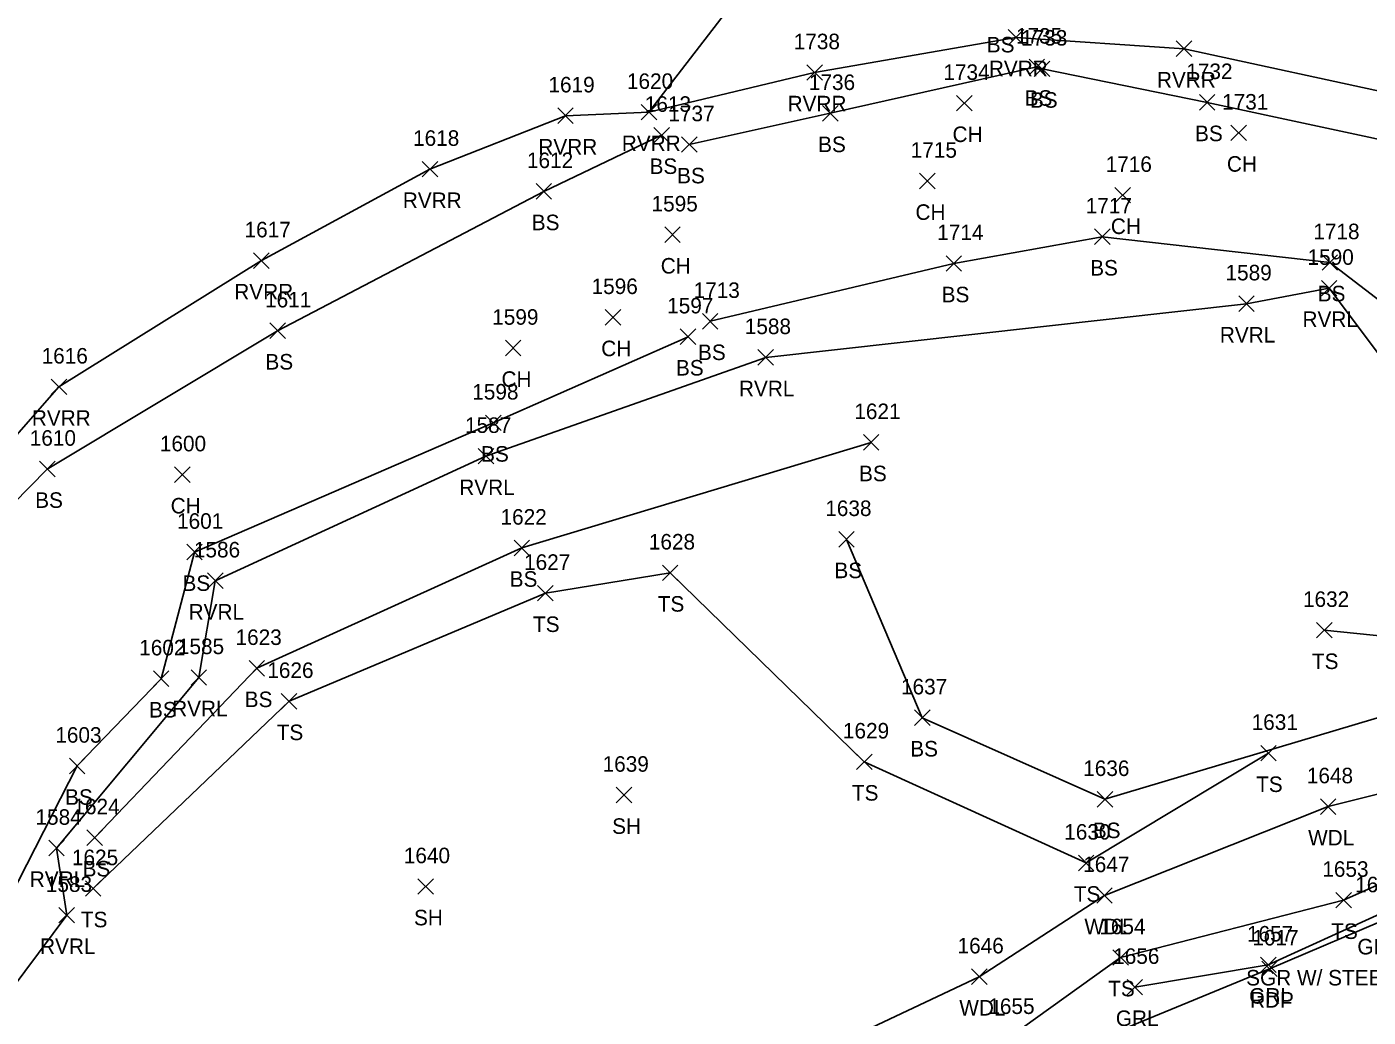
# Model space of a CAD drawing. Extents: x 1633660 to 1636532, y 388643 to 392631.
# Drawn here: x 1634224 to 1634396.6, y 388922.1 to 389049.6 of the extents above; entities that cross this region are included whole.
import ezdxf

# ---------------------------------------------------------------- set-up
doc = ezdxf.new("R2010")
doc.units = 0
for name, color, linetype in [('L_A', 7, 'Continuous'), ('L_I', 7, 'Continuous'), ('L_TIC', 7, 'Continuous'), ('LAWA', 7, 'Continuous'), ('LAWE', 7, 'Continuous'), ('LELB', 7, 'Continuous'), ('LSOGP', 7, 'Continuous'), ('P_A', 7, 'Continuous'), ('P_I', 7, 'Continuous'), ('P_TIC', 7, 'Continuous'), ('PET', 7, 'Continuous'), ('R_A', 7, 'Continuous'), ('R_C', 7, 'Continuous'), ('R_I', 7, 'Continuous'), ('R_TIC', 7, 'Continuous'), ('RGR', 7, 'Continuous')]:
    doc.layers.add(name, color=color, linetype=linetype)

msp = doc.modelspace()

# ---------------------------------------------------------------- linework, layer by layer
at = {"layer": 'L_TIC'}
for points in [[(1634350.31, 389047.27), (1634352.31, 389049.27)], [(1634352.31, 389047.27), (1634350.31, 389049.27)], [(1634371.94, 389045.82), (1634373.94, 389047.82)], [(1634373.94, 389045.82), (1634371.94, 389047.82)], [(1634352.99, 389043.47), (1634354.99, 389045.47)], [(1634354.99, 389043.47), (1634352.99, 389045.47)], [(1634353.66, 389043.22), (1634355.66, 389045.22)], [(1634355.66, 389043.22), (1634353.66, 389045.22)], [(1634324.39, 389042.75), (1634326.39, 389044.75)], [(1634326.39, 389042.75), (1634324.39, 389044.75)], [(1634343.65, 389038.8), (1634345.65, 389040.8)], [(1634345.65, 389038.8), (1634343.65, 389040.8)], [(1634374.92, 389038.91), (1634376.92, 389040.91)], [(1634376.92, 389038.91), (1634374.92, 389040.91)], [(1634292.32, 389037.19), (1634294.32, 389039.19)], [(1634294.32, 389037.19), (1634292.32, 389039.19)], [(1634303.06, 389037.64), (1634305.06, 389039.64)], [(1634305.06, 389037.64), (1634303.06, 389039.64)], [(1634326.4, 389037.5), (1634328.4, 389039.5)], [(1634328.4, 389037.5), (1634326.4, 389039.5)], [(1634304.7, 389034.69), (1634306.7, 389036.69)], [(1634306.7, 389034.69), (1634304.7, 389036.69)], [(1634378.97, 389034.98), (1634380.97, 389036.98)], [(1634380.97, 389034.98), (1634378.97, 389036.98)], [(1634308.25, 389033.48), (1634310.25, 389035.48)], [(1634310.25, 389033.48), (1634308.25, 389035.48)], [(1634274.87, 389030.31), (1634276.87, 389032.31)], [(1634276.87, 389030.31), (1634274.87, 389032.31)], [(1634338.89, 389028.78), (1634340.89, 389030.78)], [(1634340.89, 389028.78), (1634338.89, 389030.78)], [(1634289.54, 389027.45), (1634291.54, 389029.45)], [(1634291.54, 389027.45), (1634289.54, 389029.45)], [(1634364.03, 389026.96), (1634366.03, 389028.96)], [(1634366.03, 389026.96), (1634364.03, 389028.96)], [(1634306.09, 389021.87), (1634308.09, 389023.87)], [(1634308.09, 389021.87), (1634306.09, 389023.87)], [(1634361.42, 389021.61), (1634363.42, 389023.61)], [(1634363.42, 389021.61), (1634361.42, 389023.61)], [(1634253.18, 389018.53), (1634255.18, 389020.53)], [(1634255.18, 389018.53), (1634253.18, 389020.53)], [(1634342.3, 389018.17), (1634344.3, 389020.17)], [(1634344.3, 389018.17), (1634342.3, 389020.17)], [(1634390.71, 389018.29), (1634392.71, 389020.29)], [(1634392.71, 389018.29), (1634390.71, 389020.29)], [(1634390.62, 389014.99), (1634392.62, 389016.99)], [(1634392.62, 389014.99), (1634390.62, 389016.99)], [(1634379.98, 389012.99), (1634381.98, 389014.99)], [(1634381.98, 389012.99), (1634379.98, 389014.99)], [(1634298.43, 389011.23), (1634300.43, 389013.23)], [(1634300.43, 389011.23), (1634298.43, 389013.23)], [(1634310.94, 389010.73), (1634312.94, 389012.73)], [(1634312.94, 389010.73), (1634310.94, 389012.73)], [(1634255.26, 389009.51), (1634257.26, 389011.51)], [(1634257.26, 389009.51), (1634255.26, 389011.51)], [(1634308.1, 389008.74), (1634310.1, 389010.74)], [(1634310.1, 389008.74), (1634308.1, 389010.74)], [(1634285.59, 389007.28), (1634287.59, 389009.28)], [(1634287.59, 389007.28), (1634285.59, 389009.28)], [(1634318.09, 389006.07), (1634320.09, 389008.07)], [(1634320.09, 389006.07), (1634318.09, 389008.07)], [(1634227.12, 389002.28), (1634229.12, 389004.28)], [(1634229.12, 389002.28), (1634227.12, 389004.28)], [(1634283.02, 388997.65), (1634285.02, 388999.65)], [(1634285.02, 388997.65), (1634283.02, 388999.65)], [(1634331.67, 388995.13), (1634333.67, 388997.13)], [(1634333.67, 388995.13), (1634331.67, 388997.13)], [(1634282.08, 388993.35), (1634284.08, 388995.35)], [(1634284.08, 388993.35), (1634282.08, 388995.35)], [(1634225.62, 388991.7), (1634227.62, 388993.7)], [(1634227.62, 388991.7), (1634225.62, 388993.7)], [(1634243.01, 388990.98), (1634245.01, 388992.98)], [(1634245.01, 388990.98), (1634243.01, 388992.98)], [(1634286.7, 388981.54), (1634288.7, 388983.54)], [(1634288.7, 388981.54), (1634286.7, 388983.54)], [(1634328.5, 388982.65), (1634330.5, 388984.65)], [(1634330.5, 388982.65), (1634328.5, 388984.65)], [(1634244.57, 388981.01), (1634246.57, 388983.01)], [(1634246.57, 388981.01), (1634244.57, 388983.01)], [(1634305.79, 388978.34), (1634307.79, 388980.34)], [(1634307.79, 388978.34), (1634305.79, 388980.34)], [(1634247.24, 388977.32), (1634249.24, 388979.32)], [(1634249.24, 388977.32), (1634247.24, 388979.32)], [(1634289.73, 388975.72), (1634291.73, 388977.72)], [(1634291.73, 388975.72), (1634289.73, 388977.72)], [(1634389.99, 388970.95), (1634391.99, 388972.95)], [(1634391.99, 388970.95), (1634389.99, 388972.95)], [(1634252.59, 388966.05), (1634254.59, 388968.05)], [(1634254.59, 388966.05), (1634252.59, 388968.05)], [(1634240.27, 388964.71), (1634242.27, 388966.71)], [(1634242.27, 388964.71), (1634240.27, 388966.71)], [(1634245.12, 388964.87), (1634247.12, 388966.87)], [(1634247.12, 388964.87), (1634245.12, 388966.87)], [(1634256.74, 388961.8), (1634258.74, 388963.8)], [(1634258.74, 388961.8), (1634256.74, 388963.8)], [(1634338.25, 388959.69), (1634340.25, 388961.69)], [(1634340.25, 388959.69), (1634338.25, 388961.69)], [(1634229.47, 388953.47), (1634231.47, 388955.47)], [(1634231.47, 388953.47), (1634229.47, 388955.47)], [(1634330.78, 388954.01), (1634332.78, 388956.01)], [(1634332.78, 388954.01), (1634330.78, 388956.01)], [(1634382.81, 388955.12), (1634384.81, 388957.12)], [(1634384.81, 388955.12), (1634382.81, 388957.12)], [(1634299.84, 388949.73), (1634301.84, 388951.73)], [(1634301.84, 388949.73), (1634299.84, 388951.73)], [(1634361.76, 388949.18), (1634363.76, 388951.18)], [(1634363.76, 388949.18), (1634361.76, 388951.18)], [(1634390.49, 388948.24), (1634392.49, 388950.24)], [(1634392.49, 388948.24), (1634390.49, 388950.24)], [(1634231.72, 388944.25), (1634233.72, 388946.25)], [(1634233.72, 388944.25), (1634231.72, 388946.25)], [(1634226.8, 388942.9), (1634228.8, 388944.9)], [(1634228.8, 388942.9), (1634226.8, 388944.9)], [(1634359.34, 388940.99), (1634361.34, 388942.99)], [(1634361.34, 388940.99), (1634359.34, 388942.99)], [(1634274.33, 388937.95), (1634276.33, 388939.95)], [(1634276.33, 388937.95), (1634274.33, 388939.95)], [(1634231.53, 388937.7), (1634233.53, 388939.7)], [(1634233.53, 388937.7), (1634231.53, 388939.7)], [(1634361.7, 388936.8), (1634363.7, 388938.8)], [(1634363.7, 388936.8), (1634361.7, 388938.8)], [(1634392.48, 388936.2), (1634394.48, 388938.2)], [(1634394.48, 388936.2), (1634392.48, 388938.2)], [(1634228.12, 388934.26), (1634230.12, 388936.26)], [(1634230.12, 388934.26), (1634228.12, 388936.26)], [(1634363.77, 388928.81), (1634365.77, 388930.81)], [(1634365.77, 388928.81), (1634363.77, 388930.81)], [(1634345.59, 388926.34), (1634347.59, 388928.34)], [(1634347.59, 388926.34), (1634345.59, 388928.34)]]:
    msp.add_lwpolyline(points, dxfattribs=at)
at = {"layer": 'LAWA'}
msp.add_lwpolyline([(1634029.51, 388906.75), (1634042.75, 388866.2), (1634043.29, 388851.86), (1634059.73, 388819.64), (1634086.07, 388831.91), (1634132.5, 388845.49), (1634141.64, 388844.49), (1634171.78, 388858.91), (1634210.32, 388873.4), (1634220.65, 388882.43), (1634241.67, 388885.4), (1634275.37, 388895.77), (1634312.68, 388911.32), (1634346.59, 388927.34), (1634362.7, 388937.8), (1634391.49, 388949.24), (1634419.55, 388956.24), (1634431.93, 388958.02)], dxfattribs=at)
at = {"layer": 'LAWE'}
for points in [[(1634150.59, 388945.3), (1634195.7, 388949.88), (1634200.78, 388959.32), (1634202.79, 388974.39), (1634228.12, 389003.28), (1634254.18, 389019.53), (1634275.87, 389031.31), (1634293.32, 389038.19), (1634304.06, 389038.64), (1634325.39, 389043.75), (1634351.31, 389048.27), (1634372.94, 389046.82), (1634401.07, 389040.69), (1634429.33, 389021.76), (1634441.52, 388999.11), (1634453.12, 388983.42), (1634462.64, 388983.3)], [(1634146.07, 388910.13), (1634157.51, 388906.82), (1634173.76, 388910.29), (1634198.37, 388919.71), (1634216.39, 388918.22), (1634229.12, 388935.26), (1634227.8, 388943.9), (1634246.12, 388965.87), (1634248.24, 388978.32), (1634283.08, 388994.35), (1634319.09, 389007.07), (1634380.98, 389013.99), (1634391.62, 389015.99), (1634409.17, 388992.61), (1634421.79, 388970.69), (1634427.66, 388965.96), (1634434.35, 388960.52)]]:
    msp.add_lwpolyline(points, dxfattribs=at)
at = {"layer": 'LELB'}
for points in [[(1634460.79, 388973.55), (1634444.36, 388983.89), (1634433.99, 389001.98), (1634424.84, 389019.55), (1634404.32, 389033.8), (1634375.92, 389039.91), (1634354.66, 389044.22), (1634353.99, 389044.47), (1634327.4, 389038.5), (1634309.25, 389034.48)], [(1634201.17, 388949.84), (1634206.75, 388972.48), (1634226.62, 388992.7), (1634256.26, 389010.51), (1634290.54, 389028.45), (1634305.7, 389035.69)], [(1634311.94, 389011.73), (1634343.3, 389019.17), (1634362.42, 389022.61), (1634391.71, 389019.29), (1634408.61, 389006.32), (1634418.17, 388990.08), (1634439.12, 388967.17)], [(1634309.1, 389009.74), (1634284.02, 388998.65), (1634245.57, 388982.01), (1634241.27, 388965.71), (1634230.47, 388954.47), (1634220.78, 388935.48), (1634206.11, 388923.93)], [(1634332.67, 388996.13), (1634287.7, 388982.54), (1634253.59, 388967.05), (1634232.72, 388945.25)], [(1634425.9, 388965.41), (1634404.73, 388962.73), (1634362.76, 388950.18), (1634339.25, 388960.69), (1634329.5, 388983.65)], [(1634232.53, 388938.7), (1634257.74, 388962.8), (1634290.73, 388976.72), (1634306.79, 388979.34), (1634331.78, 388955.01), (1634360.34, 388941.99), (1634383.81, 388956.12)], [(1634390.99, 388971.95), (1634419.17, 388969.07)], [(1634445.58, 388960.23), (1634426.88, 388952.08), (1634393.48, 388937.2), (1634364.77, 388929.81), (1634350.49, 388919.54), (1634324.4, 388908.28), (1634285.5, 388891.78), (1634241.12, 388873.71), (1634233.64, 388876.29)]]:
    msp.add_lwpolyline(points, dxfattribs=at)
at = {"layer": 'LSOGP'}
msp.add_lwpolyline([(1634333.3, 389120.05), (1634330.26, 389110.92), (1634328.06, 389097.44), (1634317.53, 389077.59), (1634318.24, 389057.1), (1634304.06, 389038.64), (1634293.32, 389038.19), (1634275.87, 389031.31), (1634254.18, 389019.53), (1634228.12, 389003.28), (1634202.79, 388974.39)], dxfattribs=at)
at = {"layer": 'P_TIC'}
for points in [[(1634382.94, 388927.36), (1634384.94, 388929.36)], [(1634384.94, 388927.36), (1634382.94, 388929.36)]]:
    msp.add_lwpolyline(points, dxfattribs=at)
at = {"layer": 'PET'}
msp.add_lwpolyline([(1634182.59, 388846.73), (1634235.61, 388867.86), (1634289.81, 388889.55), (1634340.23, 388910.32), (1634383.94, 388928.36), (1634416.96, 388942.42), (1634441.99, 388954.99), (1634450.02, 388959.85), (1634465.24, 388958.09), (1634480.35, 388956.01), (1634458.41, 388940.87), (1634427.91, 388921.75), (1634384.73, 388901.05), (1634334.49, 388879.37), (1634279.87, 388857.15), (1634233.66, 388838.29), (1634176.14, 388816.11)], dxfattribs=at)
at = {"layer": 'R_TIC'}
for points in [[(1634382.78, 388927.87), (1634384.78, 388929.87)], [(1634384.78, 388927.87), (1634382.78, 388929.87)], [(1634365.61, 388924.99), (1634367.61, 388926.99)], [(1634367.61, 388924.99), (1634365.61, 388926.99)]]:
    msp.add_lwpolyline(points, dxfattribs=at)
at = {"layer": 'RGR'}
msp.add_lwpolyline([(1634366.61, 388925.99), (1634383.78, 388928.87), (1634397.71, 388935.21), (1634426.03, 388947.9), (1634448.04, 388959.74)], dxfattribs=at)

# ---------------------------------------------------------------- texts
at = {"layer": 'L_A'}
for s, p in [('BS', (1634347.55, 389046.34)), ('RVRR', (1634347.82, 389043.27)), ('RVRR', (1634369.45, 389041.82)), ('RVRR', (1634321.91, 389038.75)), ('BS', (1634352.43, 389039.47)), ('BS', (1634353.1, 389039.22)), ('CH', (1634343.14, 389034.8)), ('BS', (1634374.36, 389034.91)), ('RVRR', (1634289.83, 389033.19)), ('RVRR', (1634300.57, 389033.64)), ('BS', (1634325.84, 389033.5)), ('BS', (1634304.14, 389030.69)), ('BS', (1634307.69, 389029.48)), ('CH', (1634378.46, 389030.98)), ('RVRR', (1634272.38, 389026.31)), ('CH', (1634338.37, 389024.78)), ('BS', (1634288.98, 389023.45)), ('CH', (1634363.52, 389022.96)), ('CH', (1634305.58, 389017.87)), ('BS', (1634360.86, 389017.61)), ('RVRR', (1634250.69, 389014.53)), ('BS', (1634341.74, 389014.17)), ('BS', (1634390.15, 389014.29)), ('RVRL', (1634388.19, 389010.99)), ('RVRL', (1634377.55, 389008.99)), ('CH', (1634297.92, 389007.23)), ('BS', (1634254.7, 389005.51)), ('BS', (1634310.38, 389006.73)), ('BS', (1634307.54, 389004.74)), ('CH', (1634285.08, 389003.28)), ('RVRL', (1634315.65, 389002.07)), ('RVRR', (1634224.63, 388998.28)), ('BS', (1634282.46, 388993.65)), ('BS', (1634331.11, 388991.13)), ('RVRL', (1634279.65, 388989.35)), ('BS', (1634225.06, 388987.7)), ('CH', (1634242.5, 388986.98)), ('BS', (1634327.94, 388978.65)), ('BS', (1634244.02, 388977.01)), ('BS', (1634286.14, 388977.54)), ('TS', (1634305.2, 388974.34)), ('RVRL', (1634244.81, 388973.32)), ('TS', (1634289.14, 388971.72)), ('TS', (1634389.4, 388966.95)), ('BS', (1634252.03, 388962.05)), ('BS', (1634239.71, 388960.71)), ('RVRL', (1634242.69, 388960.87)), ('TS', (1634256.15, 388957.8)), ('BS', (1634337.7, 388955.69)), ('TS', (1634330.19, 388950.01)), ('TS', (1634382.22, 388951.12)), ('BS', (1634228.91, 388949.47)), ('SH', (1634299.33, 388945.73)), ('BS', (1634361.2, 388945.18)), ('WDL', (1634388.91, 388944.24)), ('BS', (1634231.16, 388940.25)), ('RVRL', (1634224.36, 388938.9)), ('TS', (1634358.75, 388936.99)), ('TS', (1634230.94, 388933.7)), ('SH', (1634273.82, 388933.95)), ('WDL', (1634360.12, 388932.8)), ('TS', (1634391.89, 388932.2)), ('RVRL', (1634225.69, 388930.26)), ('TS', (1634363.18, 388924.81)), ('WDL', (1634344.01, 388922.34))]:
    msp.add_text(s, height=2, dxfattribs=at).set_placement(p)
at = {"layer": 'L_I'}
for s, p in [('1738', (1634322.7, 389046.75)), ('1735', (1634351.3, 389047.47)), ('1733', (1634351.97, 389047.22)), ('1620', (1634301.23, 389041.64)), ('1736', (1634324.65, 389041.5)), ('1734', (1634341.96, 389042.8)), ('1732', (1634373.23, 389042.91)), ('1619', (1634291.13, 389041.19)), ('1613', (1634303.53, 389038.69)), ('1731', (1634377.84, 389038.98)), ('1737', (1634306.56, 389037.48)), ('1618', (1634273.7, 389034.31)), ('1612', (1634288.36, 389031.45)), ('1715', (1634337.76, 389032.78)), ('1716', (1634362.85, 389030.96)), ('1595', (1634304.4, 389025.87)), ('1717', (1634360.29, 389025.61)), ('1617', (1634252.01, 389022.53)), ('1714', (1634341.17, 389022.17)), ('1718', (1634389.58, 389022.29)), ('1590', (1634388.84, 389018.99)), ('1589', (1634378.28, 389016.99)), ('1596', (1634296.68, 389015.23)), ('1713', (1634309.81, 389014.73)), ('1611', (1634254.65, 389013.51)), ('1597', (1634306.41, 389012.74)), ('1599', (1634283.89, 389011.28)), ('1588', (1634316.4, 389010.07)), ('1616', (1634225.89, 389006.28)), ('1598', (1634281.32, 389001.65)), ('1621', (1634330.5, 388999.13)), ('1587', (1634280.39, 388997.35)), ('1610', (1634224.36, 388995.7)), ('1600', (1634241.11, 388994.98)), ('1638', (1634326.76, 388986.65)), ('1601', (1634243.32, 388985.01)), ('1622', (1634284.96, 388985.54)), ('1586', (1634245.49, 388981.32)), ('1628', (1634304.05, 388982.34)), ('1627', (1634287.99, 388979.72)), ('1632', (1634388.25, 388974.95)), ('1623', (1634250.85, 388970.05)), ('1602', (1634238.45, 388968.71)), ('1585', (1634243.43, 388968.87)), ('1626', (1634254.94, 388965.8)), ('1637', (1634336.51, 388963.69)), ('1631', (1634381.64, 388959.12)), ('1603', (1634227.65, 388957.47)), ('1629', (1634329.03, 388958.01)), ('1639', (1634298.1, 388953.73)), ('1636', (1634359.96, 388953.18)), ('1648', (1634388.75, 388952.24)), ('1624', (1634229.98, 388948.25)), ('1584', (1634225.1, 388946.9)), ('1630', (1634357.52, 388944.99)), ('1625', (1634229.79, 388941.7)), ('1640', (1634272.51, 388941.95)), ('1647', (1634359.96, 388940.8)), ('1653', (1634390.74, 388940.2)), ('1583', (1634226.43, 388938.26)), ('1654', (1634362.03, 388932.81)), ('1646', (1634343.79, 388930.34)), ('1655', (1634347.75, 388922.54))]:
    msp.add_text(s, height=2, dxfattribs=at).set_placement(p)
at = {"layer": 'P_A'}
msp.add_text('RDP', height=2, dxfattribs=at).set_placement((1634381.43, 388923.36))
at = {"layer": 'P_I'}
msp.add_text('1017', height=2, dxfattribs=at).set_placement((1634381.74, 388931.36))
at = {"layer": 'R_A'}
for p in [(1634395.25, 388930.21), (1634381.32, 388923.87), (1634364.16, 388920.99)]:
    msp.add_text('GRL', height=2, dxfattribs=at).set_placement(p)
at = {"layer": 'R_C'}
msp.add_text('SGR W/ STEEL POSTS', height=2, dxfattribs=at).set_placement((1634380.94, 388926.21))
at = {"layer": 'R_I'}
for s, p in [('1658', (1634394.97, 388938.21)), ('1657', (1634381.04, 388931.87)), ('1656', (1634363.82, 388928.99))]:
    msp.add_text(s, height=2, dxfattribs=at).set_placement(p)

doc.saveas('drawing.dxf')
